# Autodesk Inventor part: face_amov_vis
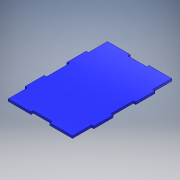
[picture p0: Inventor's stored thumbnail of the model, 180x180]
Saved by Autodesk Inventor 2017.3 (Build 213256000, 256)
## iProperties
Part Number: face_amov_vis
Material: Générique
Document SubType Name: Modeling
Designer: ficho
Density: 1 g/cm^3
Appearance: Bleu - Peinture murale - Brillant
Author: ficho
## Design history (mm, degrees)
sketch "Esquisse1"
  geometry: L1 (54.272, 133.297)-(54.272, 130.297); L2 (54.272, 130.297)-(29.572, 130.297); L3 (29.572, 130.297)-(29.572, 133.297); L4 (-0.228, 133.297)-(29.572, 133.297); L5 (54.272, 133.297)-(84.072, 133.297); L6 (54.272, 2.997)-(54.272, 5.997); L7 (54.272, 5.997)-(29.572, 5.997); L8 (29.572, 5.997)-(29.572, 2.997); L9 (84.072, 2.997)-(54.272, 2.997); L10 (29.572, 2.997)-(-0.228, 2.997); L11 (-0.228, 133.297)-(-0.228, 108.297); L12 (-0.228, 108.297)-(-3.228, 108.297); L13 (-0.228, 2.997)-(-0.228, 27.997); L14 (-0.228, 27.997)-(-3.228, 27.997); L15 (84.072, 133.297)-(84.072, 108.297); L16 (84.072, 108.297)-(87.072, 108.297); L17 (84.072, 2.997)-(84.072, 27.997); L18 (84.072, 27.997)-(87.072, 27.997); L19 (-3.228, 82.997)-(-0.228, 82.997); L20 (-0.228, 82.997)-(-0.228, 53.297); L21 (-0.228, 53.297)-(-3.228, 53.297); L22 (87.072, 82.997)-(84.072, 82.997); L23 (84.072, 82.997)-(84.072, 53.297); L24 (84.072, 53.297)-(87.072, 53.297); L25 (-3.228, 27.997)-(-3.228, 53.297); L26 (-3.228, 82.997)-(-3.228, 108.297); L27 (87.072, 108.297)-(87.072, 82.997); L28 (87.072, 53.297)-(87.072, 27.997); 1 further point
  constraints: 56 end point, 4 parallel, 2 horizontal, 2 perpendicular, 2 point on line
  dimensions: "d3" = 24.7 distance of L1.end L2.end; "d4" = 3 distance of L1.start L1.end; "d7" = 3 distance of L6.end L6.start; "d8" = 3 distance of L12.end L11.end; "d9" = 25 distance of L4.start L11.end; "d10" = 25 distance of L10.end L13.end; "d11" = 3 distance of L16.end L15.end; "d12" = 25 distance of L5.end L15.end; "d13" = 3 distance of L18.end L17.end; "d14" = 2.99701 distance from line of L10 point (0, 0); "d15" = 25.3 distance between parallel lines of L21 L14; "d16" = 2.99701 distance from line of point (0, 0) L9; "d17" = 25 distance between parallel lines of L18 L9; "d18" = 25.3 distance between parallel lines of L24 L18 (= d15); "d19" = 25 distance between parallel lines of L16 L5; "d20" = 25 distance between parallel lines of L12 L4; "d21" = 25.3 distance between parallel lines of L12 L19 (= d15); "d22" = 25.3 distance between parallel lines of L22 L16 (= d21)
extrude "Extrusion1" new body sketch "Esquisse1" distance "d23" = 3; taper "d24" = 0 deg
node "Solide1"
other parameters: "d1" = 90.3, "d2" = 130.3, "d5" = 32.8, "d6" = 32.8 (derived)
